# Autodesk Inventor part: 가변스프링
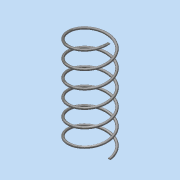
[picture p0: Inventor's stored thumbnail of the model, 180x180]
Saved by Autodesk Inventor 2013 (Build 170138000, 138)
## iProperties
Created: 2016-11
Part Number: 가변스프링
Material: 강철, 탄소
Document SubType Name: Modeling
Designer: Administrator
Mass: 14.8212 g
Surface Area: 38.0291 cm^2
Volume: 1.88326 cm^3
Density: 7.87 g/cm^3
Author: Administrator
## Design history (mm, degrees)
sketch "스케치1"
  geometry: L1 (0, 0)-(16, 0); L2 (16, 0)-(16, 84.368); L3 (16, 84.368)-(0, 84.368); L4 (0, 84.368)-(0, 0); C1 r 1 at (16, 0)
  constraints: 8 end point, 2 parallel, 1 centre point, 1 coincident, 1 horizontal, 1 perpendicular
  dimensions: "d0" = 32 diameter of L2 L4; "d2" = 84.36759 distance between parallel lines of L1 L3 (derived); "d3" = 2 diameter of C1
feature "코일1" sketch "스케치1" pitch "d4" = 10; turns "d6" = 6; dims "d5" = 84.36759 (= d2), "d7" = 0, angle "d8" = 90 deg, angle "d9" = 90 deg, "d10" = 0, "d11" = 0
node "작업 평면1"
feature "분할1"
feature "분할2"
node "솔리드1"
other parameters: "d12" = 90 deg
